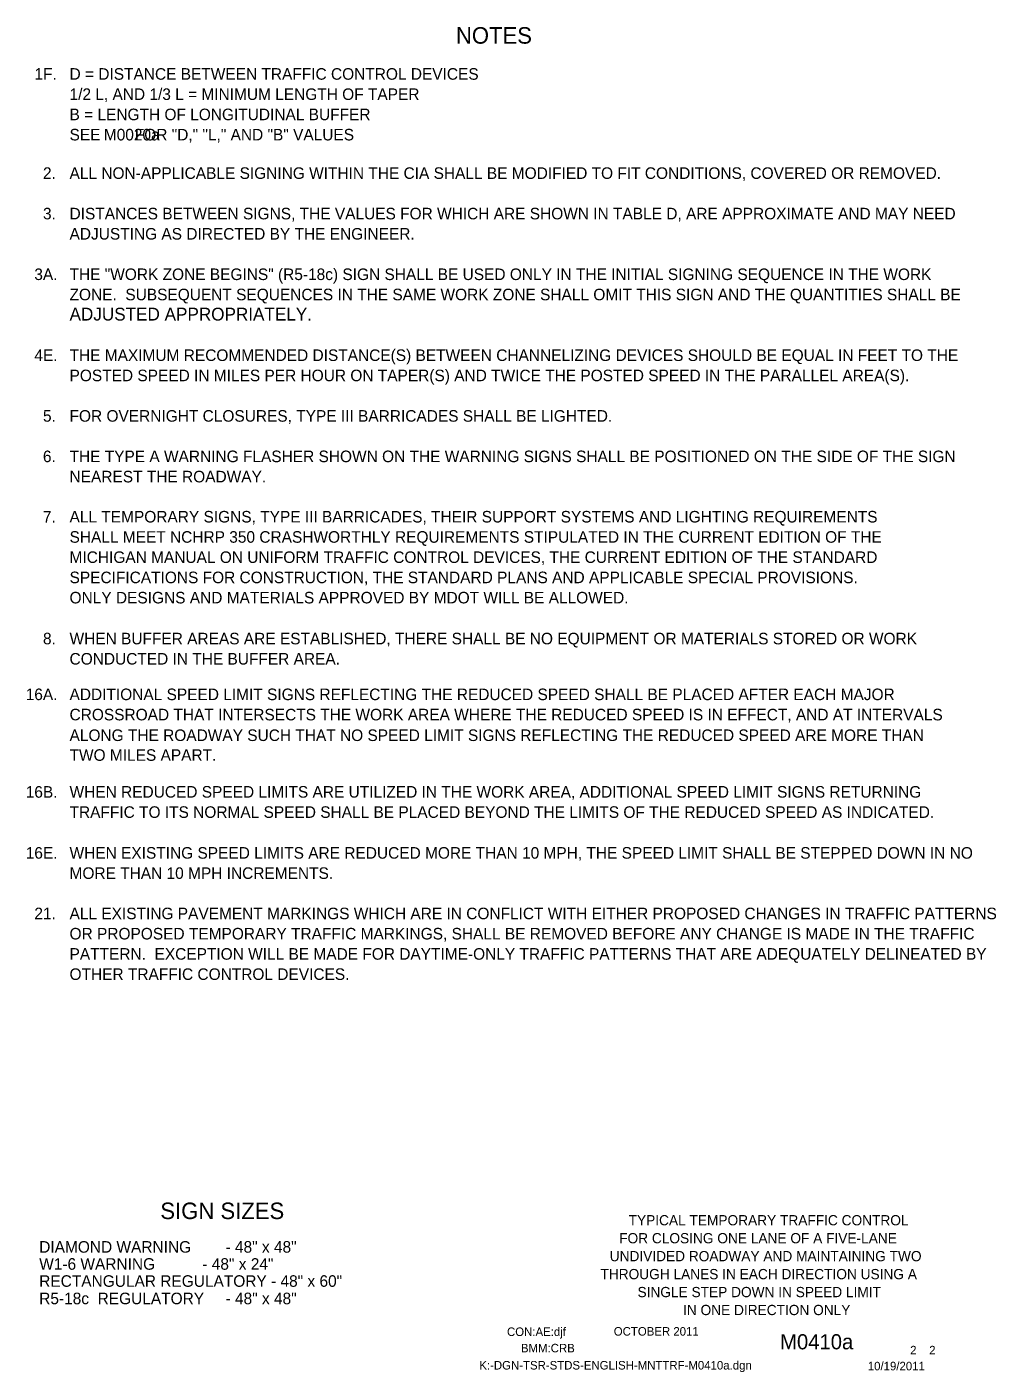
# Model space of a CAD drawing. Extents: x 16577 to 18475, y 5712 to 6919.
# Drawn here: x 17771 to 18475, y 5932 to 6909 of the extents above; entities that cross this region are included whole.
import ezdxf

# ---------------------------------------------------------------- set-up
doc = ezdxf.new("R2010")
doc.units = 0
for name, color, linetype in [('BORDER', 7, 'Continuous'), ('BORDER_SIGNAL_WO', 7, 'Continuous'), ('TYPICAL_TEXT_DIMEN_PR', 7, 'Continuous')]:
    doc.layers.add(name, color=color, linetype=linetype)

msp = doc.modelspace()

# ---------------------------------------------------------------- linework, layer by layer
at = {"layer": 'BORDER'}
msp.add_line((18318.25, 6011.25), (18318.25, 6011.25), dxfattribs=at)

# ---------------------------------------------------------------- texts
at = {"layer": 'BORDER_SIGNAL_WO'}
for s, height, p in [('TYPICAL TEMPORARY TRAFFIC CONTROL', 7.4423, (18208.1, 6038.46)), ('FOR CLOSING ONE LANE OF A FIVE-LANE', 7.4423, (18201.23, 6025.41)), ('UNDIVIDED ROADWAY AND MAINTAINING TWO', 7.4423, (18194.35, 6012.37)), ('THROUGH LANES IN EACH DIRECTION USING A', 7.4423, (18187.63, 5999.32)), ('SINGLE STEP DOWN IN SPEED LIMIT', 7.4423, (18214.55, 5986.28)), (' IN ONE DIRECTION ONLY', 7.4423, (18244.9, 5973.24)), ('CON:AE:djf', 6.2, (18119.69, 5958.06)), ('    OCTOBER 2011    ', 6.2, (18188.08, 5958.34)), ('BMM:CRB   ', 6.2, (18129.81, 5946.17)), ('    M0410a   ', 11, (18301.86, 5948.38)), (' 2    2 ', 6.2, (18410.45, 5944.7)), ('K:-DGN-TSR-STDS-ENGLISH-MNTTRF-M0410a.dgn        ', 6.2, (18099.55, 5933.71)), ('10/19/2011    ', 6.2, (18381.93, 5933.13))]:
    msp.add_text(s, height=height, dxfattribs=at).set_placement(p)
at = {"layer": 'TYPICAL_TEXT_DIMEN_PR'}
for s, height, p in [('NOTES', 12, (18082.55, 6897)), ('1F.', 8.4, (17776.19, 6870.8)), ('D = DISTANCE BETWEEN TRAFFIC CONTROL DEVICES', 8.4, (17801.7, 6870.8)), ('1/2 L, AND 1/3 L = MINIMUM LENGTH OF TAPER', 8.4, (17801.7, 6856.1)), ('B = LENGTH OF LONGITUDINAL BUFFER', 8.4, (17801.7, 6841.4)), ('SEE        FOR "D," "L," AND "B" VALUES', 8.4, (17801.7, 6826.7)), ('M0020a', 8.4, (17826.62, 6826.7)), ('2.', 8.4, (17782.39, 6798.75)), ('ALL NON-APPLICABLE SIGNING WITHIN THE CIA SHALL BE MODIFIED TO FIT CONDITIONS, COVERED OR REMOVED.', 8.4, (17801.7, 6798.75)), ('3.', 8.4, (17782.39, 6769.35)), ('DISTANCES BETWEEN SIGNS, THE VALUES FOR WHICH ARE SHOWN IN TABLE D, ARE APPROXIMATE AND MAY NEED', 8.4, (17801.7, 6769.35)), ('ADJUSTING AS DIRECTED BY THE ENGINEER.', 8.4, (17801.7, 6754.65)), ('THE "WORK ZONE BEGINS" (R5-18c) SIGN SHALL BE USED ONLY IN THE INITIAL SIGNING SEQUENCE IN THE WORK', 8.4, (17801.7, 6725.25)), ('3A.', 8.4, (17776.09, 6725.25)), ('ZONE.  SUBSEQUENT SEQUENCES IN THE SAME WORK ZONE SHALL OMIT THIS SIGN AND THE QUANTITIES SHALL BE', 8.4, (17801.7, 6710.55)), ('ADJUSTED APPROPRIATELY.', 9.3, (17801.7, 6695.85)), ('THE MAXIMUM RECOMMENDED DISTANCE(S) BETWEEN CHANNELIZING DEVICES SHOULD BE EQUAL IN FEET TO THE', 8.4, (17801.7, 6666.45)), ('4E.', 8.4, (17776.13, 6666.45)), ('POSTED SPEED IN MILES PER HOUR ON TAPER(S) AND TWICE THE POSTED SPEED IN THE PARALLEL AREA(S).', 8.4, (17801.7, 6651.75)), ('5.', 8.4, (17782.39, 6622.35)), ('FOR OVERNIGHT CLOSURES, TYPE III BARRICADES SHALL BE LIGHTED.', 8.4, (17801.7, 6622.35)), ('6.', 8.4, (17782.34, 6592.95)), ('THE TYPE A WARNING FLASHER SHOWN ON THE WARNING SIGNS SHALL BE POSITIONED ON THE SIDE OF THE SIGN', 8.4, (17801.7, 6592.95)), ('NEAREST THE ROADWAY.', 8.4, (17801.7, 6578.25)), ('7.', 8.4, (17782.34, 6549.09)), ('ALL TEMPORARY SIGNS, TYPE III BARRICADES, THEIR SUPPORT SYSTEMS AND LIGHTING REQUIREMENTS', 8.4, (17801.7, 6549.11)), ('SHALL MEET NCHRP 350 CRASHWORTHLY REQUIREMENTS STIPULATED IN THE CURRENT EDITION OF THE', 8.4, (17801.7, 6534.41)), ('MICHIGAN MANUAL ON UNIFORM TRAFFIC CONTROL DEVICES, THE CURRENT EDITION OF THE STANDARD', 8.4, (17801.7, 6519.71)), ('SPECIFICATIONS FOR CONSTRUCTION, THE STANDARD PLANS AND APPLICABLE SPECIAL PROVISIONS.', 8.4, (17801.7, 6505.01)), ('ONLY DESIGNS AND MATERIALS APPROVED BY MDOT WILL BE ALLOWED.', 8.4, (17801.7, 6490.31)), ('8.', 8.4, (17782.39, 6460.58)), ('WHEN BUFFER AREAS ARE ESTABLISHED, THERE SHALL BE NO EQUIPMENT OR MATERIALS STORED OR WORK     ', 8.4, (17801.7, 6460.58)), ('CONDUCTED IN THE BUFFER AREA.', 8.4, (17801.7, 6445.88)), ('16A.', 8.4, (17769.83, 6420.05)), ('ADDITIONAL SPEED LIMIT SIGNS REFLECTING THE REDUCED SPEED SHALL BE PLACED AFTER EACH MAJOR', 8.4, (17801.7, 6420.05)), ('CROSSROAD THAT INTERSECTS THE WORK AREA WHERE THE REDUCED SPEED IS IN EFFECT, AND AT INTERVALS', 8.4, (17801.7, 6405.35)), ('ALONG THE ROADWAY SUCH THAT NO SPEED LIMIT SIGNS REFLECTING THE REDUCED SPEED ARE MORE THAN', 8.4, (17801.7, 6390.35)), ('TWO MILES APART.', 8.4, (17801.7, 6375.95)), ('16B.', 8.4, (17769.84, 6349.16)), ('WHEN REDUCED SPEED LIMITS ARE UTILIZED IN THE WORK AREA, ADDITIONAL SPEED LIMIT SIGNS RETURNING', 8.4, (17801.7, 6349.21)), ('TRAFFIC TO ITS NORMAL SPEED SHALL BE PLACED BEYOND THE LIMITS OF THE REDUCED SPEED AS INDICATED.', 8.4, (17801.7, 6334.51)), ('16E.', 8.4, (17769.84, 6304.86)), ('WHEN EXISTING SPEED LIMITS ARE REDUCED MORE THAN 10 MPH, THE SPEED LIMIT SHALL BE STEPPED DOWN IN NO', 8.4, (17801.7, 6304.86)), ('MORE THAN 10 MPH INCREMENTS.', 8.4, (17801.7, 6290.16)), ('21.', 8.4, (17776.13, 6260.86)), ('ALL EXISTING PAVEMENT MARKINGS WHICH ARE IN CONFLICT WITH EITHER PROPOSED CHANGES IN TRAFFIC PATTERNS', 8.4, (17801.7, 6260.86)), ('OR PROPOSED TEMPORARY TRAFFIC MARKINGS, SHALL BE REMOVED BEFORE ANY CHANGE IS MADE IN THE TRAFFIC', 8.4, (17801.7, 6246.16)), ('PATTERN.  EXCEPTION WILL BE MADE FOR DAYTIME-ONLY TRAFFIC PATTERNS THAT ARE ADEQUATELY DELINEATED BY', 8.4, (17801.7, 6231.46)), ('OTHER TRAFFIC CONTROL DEVICES.', 8.4, (17801.7, 6216.76)), ('SIGN SIZES', 12, (17867.69, 6043)), ('DIAMOND WARNING        - 48" x 48"', 8.4, (17779.65, 6018.6)), ('W1-6 WARNING           - 48" x 24"', 8.4, (17779.65, 6006.2)), ('RECTANGULAR REGULATORY - 48" x 60"', 8.4, (17779.65, 5993.8)), ('R5-18c  REGULATORY     - 48" x 48"', 8.4, (17779.65, 5981.15))]:
    msp.add_text(s, height=height, dxfattribs=at).set_placement(p)

doc.saveas('drawing.dxf')
